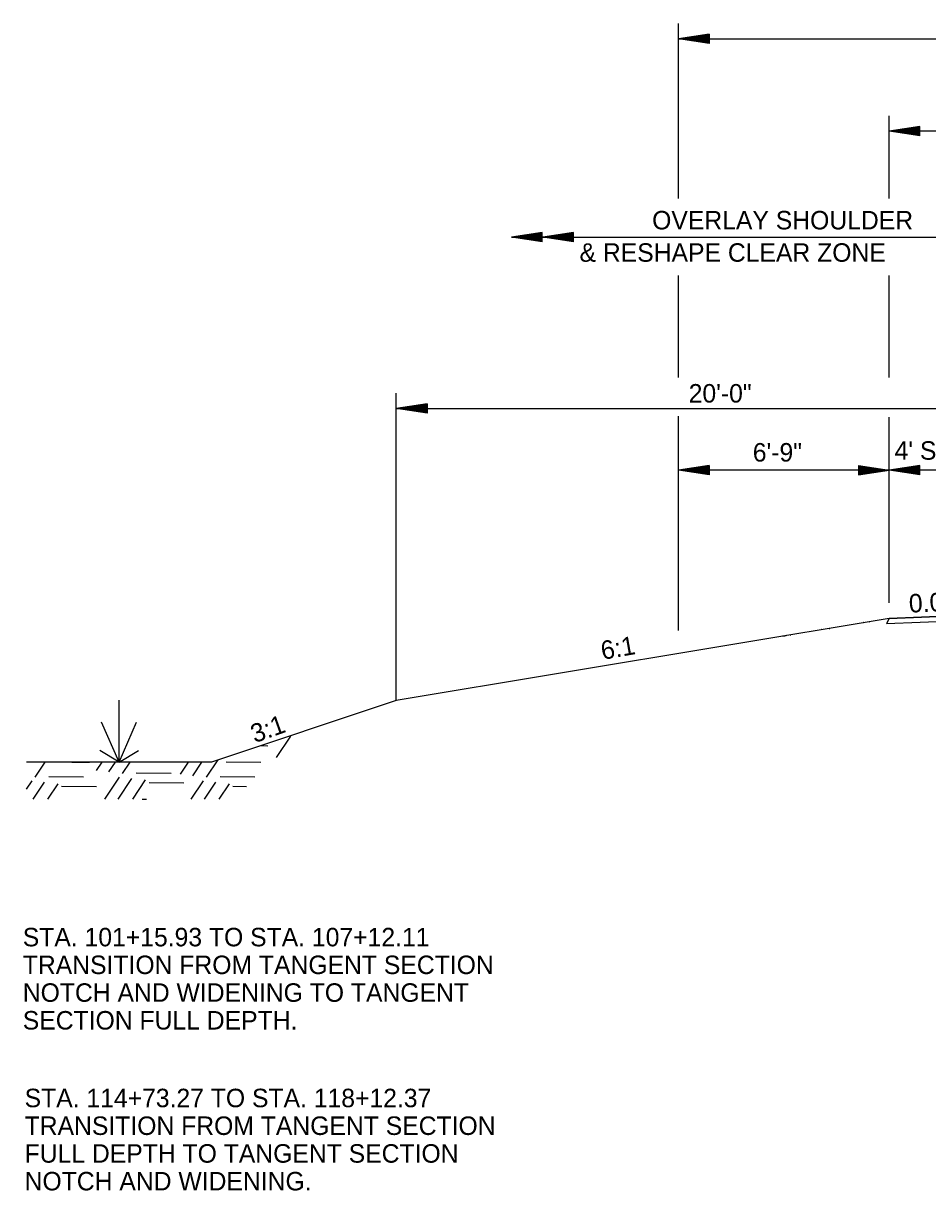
# Model space of a CAD drawing. Extents: x -900 to 15312, y 1857 to 2945.
# Drawn here: x -900.4 to -606.8, y 2037.3 to 2416.2 of the extents above; entities that cross this region are included whole.
import ezdxf

# ---------------------------------------------------------------- set-up
doc = ezdxf.new("R2010")
doc.units = 0
for name, color, linetype in [('R_Annotation', 7, 'Continuous'), ('R_Dimension', 7, 'Continuous'), ('R_Draft', 7, 'Continuous')]:
    doc.layers.add(name, color=color, linetype=linetype)

msp = doc.modelspace()

# ---------------------------------------------------------------- linework, layer by layer
at = {"layer": 'R_Annotation'}
for p, q in [((-619.31, 2223.11), (-579.31, 2224.71)), ((-619.31, 2223.11), (-779.31, 2196.44)), ((-619.31, 2223.11), (-620.16, 2221.4)), ((-779.31, 2196.44), (-839.31, 2176.44)), ((-839.31, 2176.44), (-899.31, 2176.44))]:
    msp.add_line(p, q, dxfattribs=at)
for points in [[(-633.47, 2220.74), (-633.47, 2220.74), (-633.47, 2220.74), (-633.47, 2220.74)], [(-633.41, 2220.74), (-633.41, 2220.75), (-633.41, 2220.75), (-633.41, 2220.75)], [(-627.57, 2221.73), (-627.62, 2221.72), (-627.67, 2221.71), (-627.72, 2221.7)], [(-625.79, 2222.02), (-625.79, 2222.02), (-625.79, 2222.02), (-625.79, 2222.02)], [(-625.79, 2222.02), (-625.77, 2222.02), (-625.75, 2222.02), (-625.73, 2222.02)], [(-652.52, 2217.57), (-652.56, 2217.55), (-652.89, 2217.45), (-653.22, 2217.36), (-653.64, 2217.34), (-653.77, 2217.33), (-653.89, 2217.34)], [(-651.39, 2217.68), (-651.37, 2217.68), (-651.35, 2217.68), (-651.33, 2217.68)], [(-641.15, 2219.44), (-641.18, 2219.44), (-641.22, 2219.44), (-641.26, 2219.44), (-641.27, 2219.44)], [(-638.83, 2219.85), (-638.75, 2219.85), (-638.67, 2219.85), (-638.59, 2219.84)]]:
    msp.add_open_spline(points, degree=3, dxfattribs=at)
at = {"layer": 'R_Dimension'}
for p, q in [((-687.73, 2359.34), (-687.73, 2416.24)), ((-677.73, 2412.74), (-687.73, 2411.24)), ((-687.73, 2411.24), (-250.88, 2411.24)), ((-677.73, 2409.74), (-687.73, 2411.24)), ((-677.73, 2412.49), (-686.06, 2411.24)), ((-677.73, 2409.99), (-686.06, 2411.24)), ((-677.73, 2412.23), (-684.34, 2411.24)), ((-677.73, 2410.24), (-684.34, 2411.24)), ((-677.73, 2411.98), (-682.68, 2411.24)), ((-677.73, 2410.49), (-682.68, 2411.24)), ((-677.73, 2411.72), (-680.98, 2411.24)), ((-677.73, 2410.75), (-680.98, 2411.24)), ((-677.73, 2411.47), (-679.31, 2411.24)), ((-677.73, 2411), (-679.31, 2411.24)), ((-677.73, 2412.74), (-677.73, 2409.74)), ((-619.31, 2359.34), (-619.31, 2386.24)), ((-609.31, 2382.74), (-619.31, 2381.24)), ((-319.31, 2381.24), (-619.31, 2381.24)), ((-609.31, 2379.74), (-619.31, 2381.24)), ((-609.31, 2382.49), (-617.64, 2381.24)), ((-609.31, 2379.99), (-617.64, 2381.24)), ((-609.31, 2382.23), (-615.92, 2381.24)), ((-609.31, 2380.24), (-615.92, 2381.24)), ((-609.31, 2381.98), (-614.25, 2381.24)), ((-609.31, 2380.49), (-614.25, 2381.24)), ((-609.31, 2381.73), (-612.56, 2381.24)), ((-609.31, 2380.75), (-612.56, 2381.24)), ((-609.31, 2381.47), (-610.89, 2381.24)), ((-609.31, 2381), (-610.89, 2381.24)), ((-609.31, 2379.74), (-609.31, 2382.74)), ((-731.93, 2348.34), (-741.93, 2346.84)), ((-741.93, 2346.84), (-300.92, 2346.84)), ((-731.93, 2345.34), (-741.93, 2346.84)), ((-731.93, 2348.09), (-740.26, 2346.84)), ((-731.93, 2345.59), (-740.26, 2346.84)), ((-731.93, 2347.83), (-738.54, 2346.84)), ((-731.93, 2345.84), (-738.54, 2346.84)), ((-731.93, 2347.58), (-736.88, 2346.84)), ((-731.93, 2346.09), (-736.88, 2346.84)), ((-731.93, 2347.33), (-735.18, 2346.84)), ((-731.93, 2346.35), (-735.18, 2346.84)), ((-731.93, 2347.07), (-733.51, 2346.84)), ((-731.93, 2346.6), (-733.51, 2346.84)), ((-731.93, 2345.34), (-731.93, 2348.34)), ((-721.77, 2348.34), (-731.77, 2346.84)), ((-721.77, 2345.34), (-731.77, 2346.84)), ((-721.77, 2348.09), (-730.1, 2346.84)), ((-721.77, 2345.59), (-730.1, 2346.84)), ((-721.77, 2347.83), (-728.38, 2346.84)), ((-721.77, 2345.84), (-728.38, 2346.84)), ((-721.77, 2347.58), (-726.71, 2346.84)), ((-721.77, 2346.09), (-726.71, 2346.84)), ((-721.77, 2347.33), (-725.02, 2346.84)), ((-721.77, 2346.35), (-725.02, 2346.84)), ((-721.77, 2347.07), (-723.35, 2346.84)), ((-721.77, 2346.6), (-723.35, 2346.84)), ((-721.77, 2345.34), (-721.77, 2348.34)), ((-687.73, 2301.32), (-687.73, 2334.34)), ((-619.31, 2301.32), (-619.31, 2334.34)), ((-779.31, 2196.44), (-779.31, 2296.24)), ((-769.31, 2292.74), (-779.31, 2291.24)), ((-769.31, 2292.49), (-777.64, 2291.24)), ((-769.31, 2292.74), (-769.31, 2289.74)), ((-769.31, 2289.74), (-779.31, 2291.24)), ((-779.31, 2291.24), (-579.31, 2291.24)), ((-769.31, 2289.99), (-777.64, 2291.24)), ((-769.31, 2292.23), (-775.92, 2291.24)), ((-769.31, 2290.24), (-775.92, 2291.24)), ((-769.31, 2291.98), (-774.26, 2291.24)), ((-769.31, 2290.49), (-774.26, 2291.24)), ((-769.31, 2291.72), (-772.56, 2291.24)), ((-769.31, 2290.75), (-772.56, 2291.24)), ((-769.31, 2291.47), (-770.89, 2291.24)), ((-769.31, 2291), (-770.89, 2291.24)), ((-687.73, 2219.16), (-687.73, 2288.74)), ((-619.31, 2228.11), (-619.31, 2288.36)), ((-619.31, 2228.11), (-619.31, 2276.24)), ((-677.73, 2272.74), (-687.73, 2271.24)), ((-250.88, 2271.24), (-687.73, 2271.24)), ((-677.73, 2269.74), (-687.73, 2271.24)), ((-677.73, 2272.49), (-686.06, 2271.24)), ((-677.73, 2269.99), (-686.06, 2271.24)), ((-677.73, 2272.23), (-684.34, 2271.24)), ((-677.73, 2270.24), (-684.34, 2271.24)), ((-677.73, 2271.98), (-682.68, 2271.24)), ((-677.73, 2270.49), (-682.68, 2271.24)), ((-677.73, 2271.72), (-680.98, 2271.24)), ((-677.73, 2270.75), (-680.98, 2271.24)), ((-677.73, 2271.47), (-679.31, 2271.24)), ((-677.73, 2271), (-679.31, 2271.24)), ((-677.73, 2272.74), (-677.73, 2269.74)), ((-629.31, 2272.74), (-619.31, 2271.24)), ((-629.31, 2272.74), (-629.31, 2269.74)), ((-629.31, 2272.49), (-620.98, 2271.24)), ((-629.31, 2272.23), (-622.7, 2271.24)), ((-629.31, 2271.98), (-624.36, 2271.24)), ((-629.31, 2271.72), (-626.06, 2271.24)), ((-629.31, 2271.47), (-627.73, 2271.24)), ((-629.31, 2269.74), (-619.31, 2271.24)), ((-629.31, 2270.75), (-626.06, 2271.24)), ((-629.31, 2270.24), (-622.7, 2271.24)), ((-629.31, 2269.99), (-620.98, 2271.24)), ((-629.31, 2270.49), (-624.36, 2271.24)), ((-629.31, 2271), (-627.73, 2271.24)), ((-609.31, 2272.74), (-619.31, 2271.24)), ((-609.31, 2269.74), (-619.31, 2271.24)), ((-609.31, 2272.49), (-617.64, 2271.24)), ((-609.31, 2269.99), (-617.64, 2271.24)), ((-609.31, 2272.23), (-615.92, 2271.24)), ((-609.31, 2270.24), (-615.92, 2271.24)), ((-609.31, 2271.98), (-614.25, 2271.24)), ((-609.31, 2270.49), (-614.25, 2271.24)), ((-609.31, 2271.73), (-612.56, 2271.24)), ((-609.31, 2270.75), (-612.56, 2271.24)), ((-609.31, 2271.47), (-610.89, 2271.24)), ((-609.31, 2271), (-610.89, 2271.24)), ((-609.31, 2269.74), (-609.31, 2272.74)), ((-579.31, 2224.71), (-619.31, 2223.11)), ((-619.31, 2223.11), (-620.16, 2221.4)), ((-620.16, 2221.4), (-580.16, 2223)), ((-818.17, 2177.92), (-813.51, 2184.83)), ((-823.26, 2181.79), (-821.02, 2181.77)), ((-896.57, 2171.57), (-893.28, 2176.44)), ((-884.6, 2176.44), (-878.86, 2176.39)), ((-876.64, 2173.7), (-874.79, 2176.44)), ((-872.65, 2173.24), (-870.49, 2176.44)), ((-868.2, 2172.77), (-865.73, 2176.44)), ((-849.38, 2172.5), (-846.72, 2176.44)), ((-845.4, 2172.03), (-842.42, 2176.44)), ((-840.95, 2171.57), (-837.18, 2177.15)), ((-834.55, 2176.48), (-823.24, 2176.39)), ((-892.12, 2171.75), (-880.81, 2171.66)), ((-873.95, 2164.42), (-869.13, 2171.57)), ((-869.65, 2164.42), (-865.14, 2171.1)), ((-863.75, 2172.96), (-852.44, 2172.87)), ((-836.5, 2171.75), (-825.19, 2171.66)), ((-899.31, 2167.67), (-897.49, 2170.36)), ((-897.21, 2164.42), (-893.51, 2169.9)), ((-892.44, 2164.42), (-889.06, 2169.44)), ((-887.95, 2168.6), (-876.64, 2168.51)), ((-864.89, 2164.42), (-860.69, 2170.64)), ((-859.58, 2169.81), (-848.27, 2169.71)), ((-845.89, 2164.42), (-841.87, 2170.36)), ((-841.59, 2164.42), (-837.89, 2169.9)), ((-836.82, 2164.42), (-833.44, 2169.44)), ((-832.33, 2168.6), (-827.9, 2168.56)), ((-861.8, 2164.43), (-860.45, 2164.42))]:
    msp.add_line(p, q, dxfattribs=at)
at = {"layer": 'R_Draft'}
for q in [(-869.31, 2196.53), (-875, 2189.37), (-863.62, 2189.37), (-875.6, 2180.23), (-863.02, 2180.23)]:
    msp.add_line((-869.31, 2176.44), q, dxfattribs=at)

# ---------------------------------------------------------------- texts
at = {"layer": 'R_Annotation'}
for s, p in [('OVERLAY SHOULDER', (-696.25, 2349.35)), ('& RESHAPE CLEAR ZONE', (-719.82, 2338.85)), ('20\'-0"', (-684.39, 2293.15)), ('6\'-9"', (-663.58, 2274)), ("4' SHLD.", (-617.54, 2274.59)), ('STA. 101+15.93 TO STA. 107+12.11', (-900.57, 2116.64)), ('TRANSITION FROM TANGENT SECTION', (-900.57, 2107.64)), ('NOTCH AND WIDENING TO TANGENT ', (-900.57, 2098.64)), ('SECTION FULL DEPTH. ', (-900.57, 2089.64)), ('STA. 114+73.27 TO STA. 118+12.37', (-899.97, 2064.42)), ('TRANSITION FROM TANGENT SECTION', (-899.97, 2055.42)), ('FULL DEPTH TO TANGENT SECTION ', (-899.97, 2046.42)), ('NOTCH AND WIDENING.', (-899.97, 2037.42))]:
    msp.add_text(s, height=6, dxfattribs=at).set_placement(p)
for s, rotation, p in [("0.04'/'", 2.7804, (-612.76, 2224.93)), ('6:1', 9.9734, (-712.34, 2209.62)), ('3:1', 19.6286, (-825.29, 2182.57))]:
    msp.add_text(s, height=6, rotation=rotation, dxfattribs=at).set_placement(p)

doc.saveas('drawing.dxf')
